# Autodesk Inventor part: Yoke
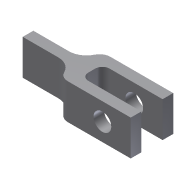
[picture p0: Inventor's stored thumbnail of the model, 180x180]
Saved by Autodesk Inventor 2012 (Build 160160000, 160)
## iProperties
Created: 2012-02
Part Number: Yoke
Material: Default
Document SubType Name: Modeling
Designer: cadcim
Density: 1 g/cm^3
Author: cadcim
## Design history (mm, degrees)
sketch "Sketch1"
  geometry: L1 (-20, 1.5)-(-9.975, 1.5); L2 (-5, 6)-(15, 6); L3 (15, 6)-(15, 3); L4 (15, 3)-(-2, 3); L5 (0, 0)-(-12.291, 0); L6 (-20, -1.5)-(-9.975, -1.5); L7 (-5, -6)-(15, -6); L8 (15, -6)-(15, -3); L9 (15, -3)-(-2, -3); L10 (-20, 1.5)-(-20, -1.5); L11 (-2, 3)-(-2, -3); A1 r 5 centre (-9.975, 6.5) between (-9.975, 1.5) and (-5, 6); A2 r 5 centre (-9.975, -6.5) between (-5, -6) and (-9.975, -1.5)
  constraints: 22 end point, 7 symmetric about line, 4 point on circle, 3 parallel, 2 centre point, 1 horizontal, 1 perpendicular, 1 tangent, 1 other
  dimensions: "d0" = 3 distance of L1.start L6.start; "d1" = 20 distance of L2.start L2.end; "d2" = 6 distance between parallel lines of L9 L4; "d3" = 3 distance of L7.end L8.end; "d4" = 5 radius of A1; "d5" = 35 distance between parallel lines of L10 L8; "d12" = 17 distance of L3.end L4.end
extrude "Extrusion1" new body sketch "Sketch1" stored distance "d8" = 10; taper "d9" = 0 deg
fillet "Fillet1" dims "d10" = 3
fillet "Fillet2" dims "d11" = 2
sketch "Sketch2"
  geometry: L1 (0, 0)-(0, 10) reference; L2 (-17.781, 0)-(0, 0) reference; C1 r 2.5 at (-8, 5); 1 further point
  constraints: 1 centre point
  dimensions: "d13" = 5 diameter of C1; "d16" = 8 distance from line of L1 C1.centre; "d17" = 5 distance from line of C1.centre L2
extrude "Extrusion2" cut sketch "Sketch2" distance "d18" = 20.25; taper "d19" = 0 deg
body "Solid1"
